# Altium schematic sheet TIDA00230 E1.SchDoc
size 431 x 279 mm; Date: Not shown in title block; ApprovedBy: Not shown in title block; CheckedBy: Not shown in title block; Author: Not shown in title block; CompanyName: Not shown in title block; DrawnBy: M. Chevrier; Engineer: Not shown in title block; Organization: Not shown in title block; Address1: Not shown in title block; Address2: Not shown in title block; Address3: Not shown in title block; Address4: Not shown in title block; DocumentNumber: 1; Revision: Use project parameter SCH_Rev; SheetNumber: 1; SheetTotal: 1; PageSetup: Record=PageOptions|CenterHorizontal=True|CenterVertical=True|PrintScale=0.94|XCorrection=1.00|YCorrection=1.00|PrintKind=0|BorderSize=5000000|LeftOffset=0|BottomOffset=0|Orientation=2|PaperLength=4200|PaperWidth=2970|Scale=100|PaperSource=7|PrintQuality=600|MediaType=1|DitherType=10|PaperKind=A3|PrintScaleMode=1
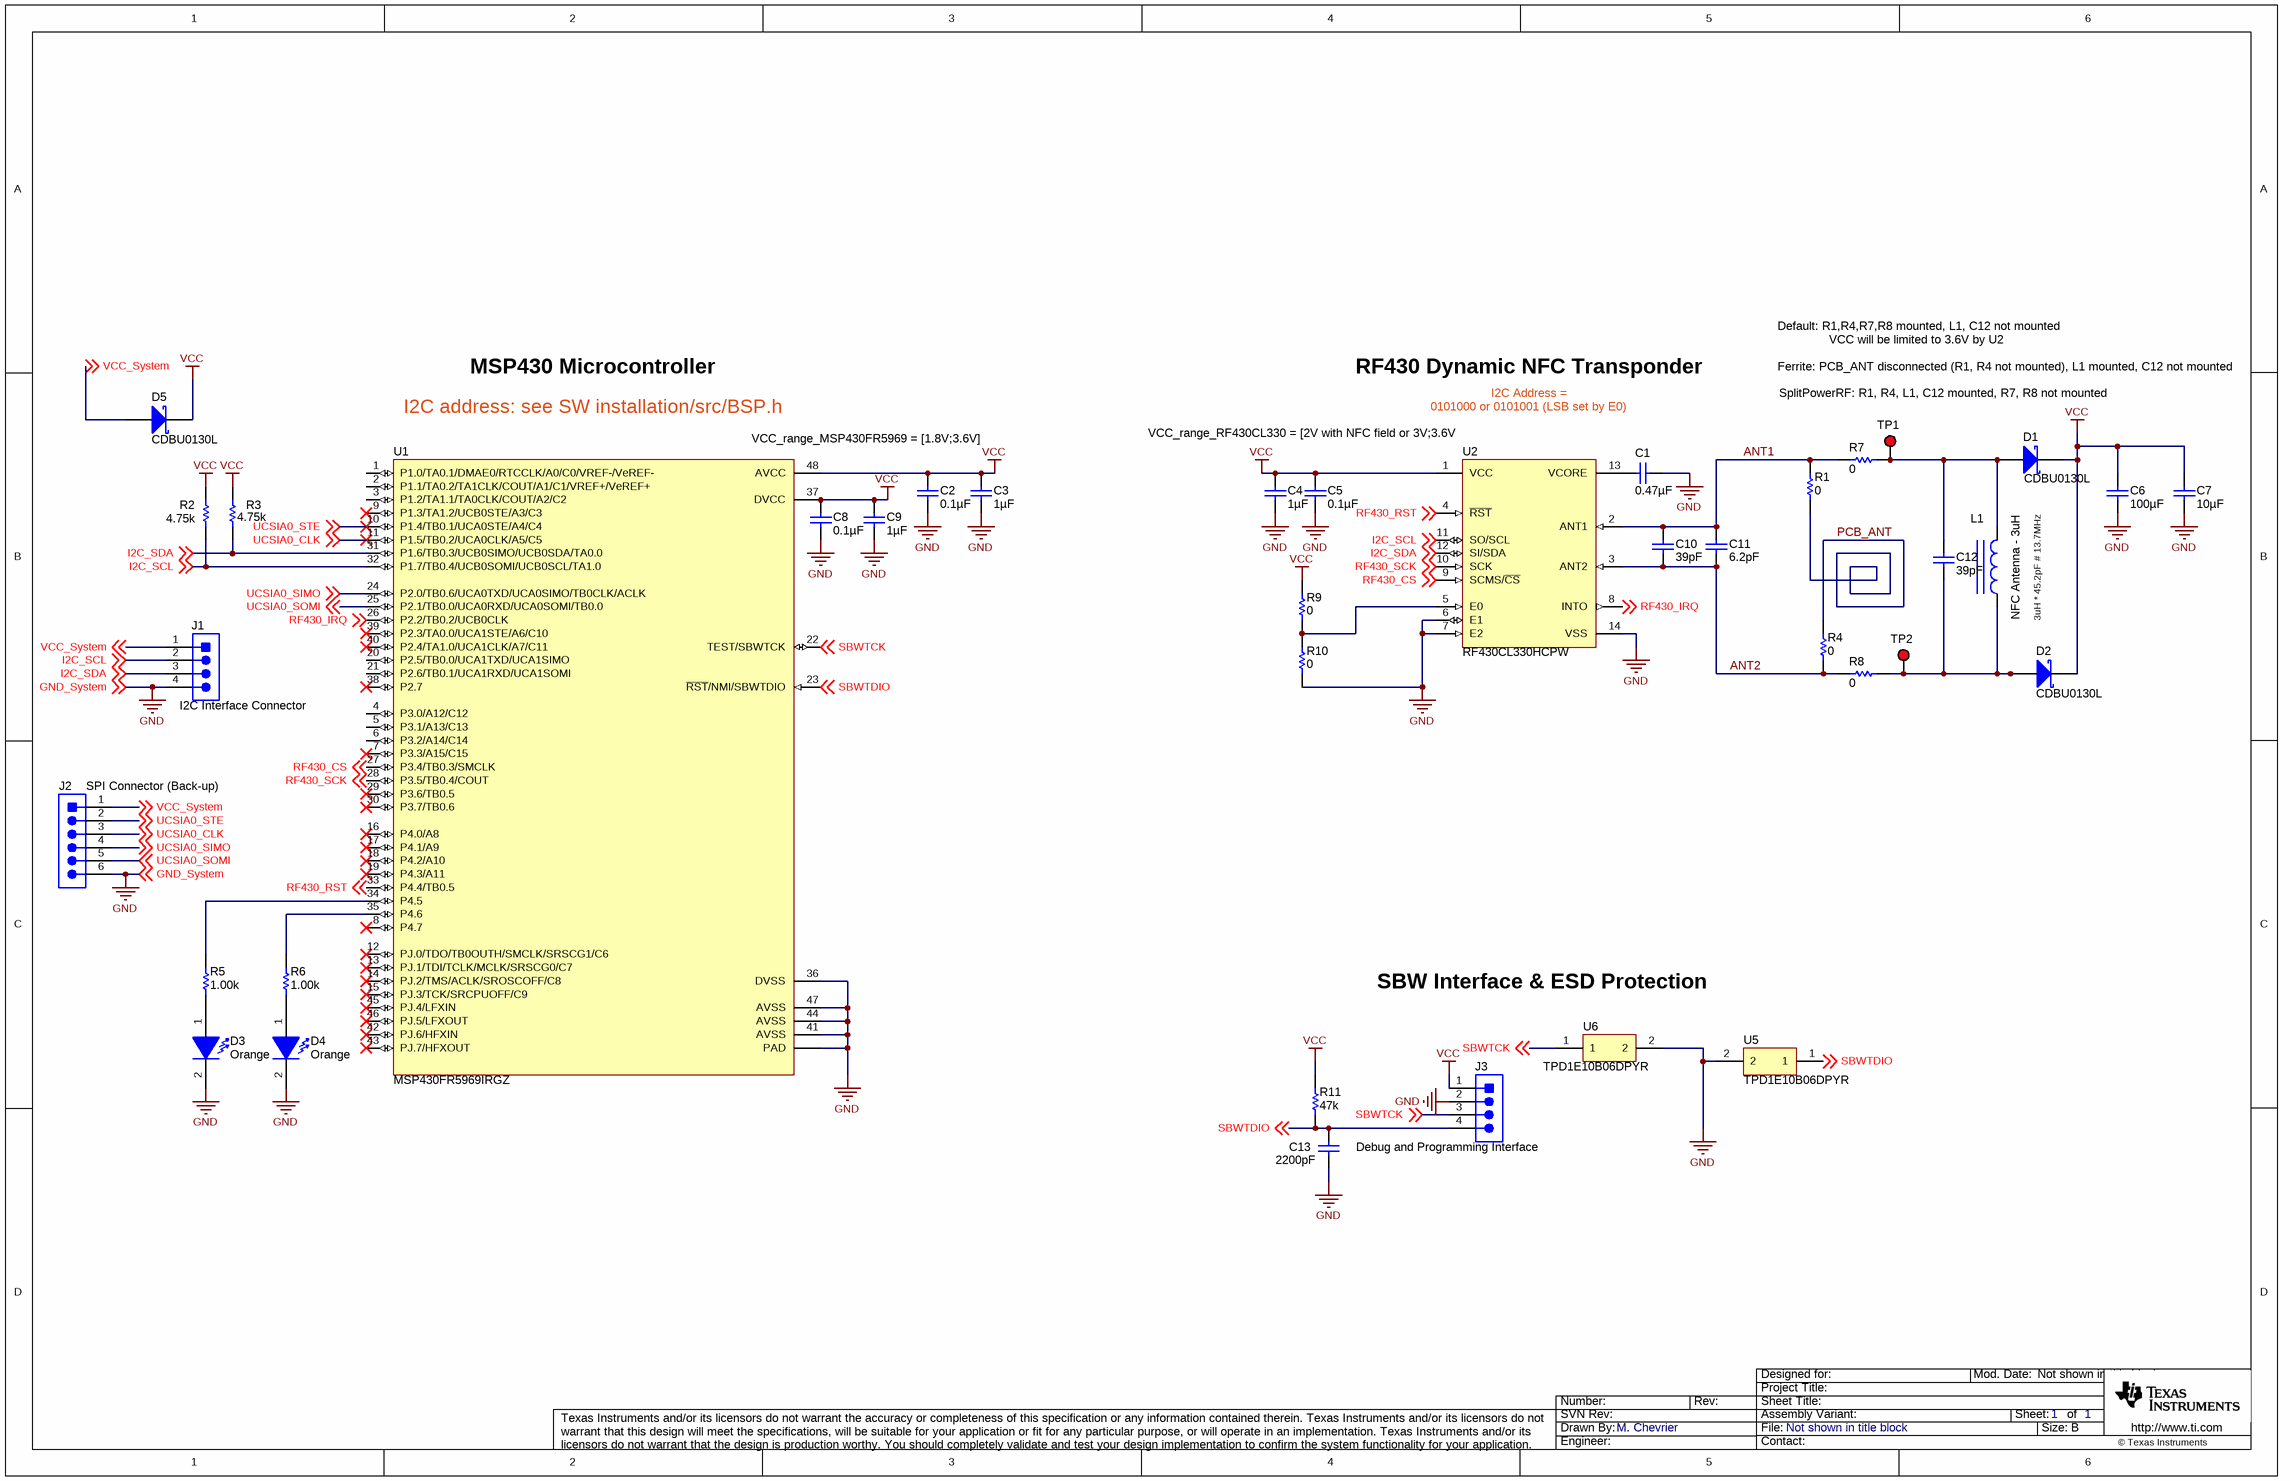
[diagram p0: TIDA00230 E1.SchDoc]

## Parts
C1  ValueDisplayed: 0.47µF  [0603S]  (hidden comment: GRM188R71E474KA12D)
C2  ValueDisplayed: 0.1µF  [0402S]  (hidden comment: GRM155R71C104KA88D)
C3  ValueDisplayed: 1µF  [0603S]  (hidden comment: GRM188R71C105KA12D)
C4  ValueDisplayed: 1µF  [0603S]  (hidden comment: GRM188R71C105KA12D)
C5  ValueDisplayed: 0.1µF  [0402S]  (hidden comment: GRM155R71C104KA88D)
C6  ValueDisplayed: 100µF  [1206_190]  (hidden comment: C3216X5R1A107M160AC)
C7  ValueDisplayed: 10µF  [0402S]  (hidden comment: CL05A106MP5NUNC)
C8  ValueDisplayed: 0.1µF  [0402S]  (hidden comment: GRM155R71C104KA88D)
C9  ValueDisplayed: 1µF  [0603S]  (hidden comment: GRM188R71C105KA12D)
C10  ValueDisplayed: 39pF  [0402S]  (hidden comment: GRM1555C1H390JA01D)
C11  ValueDisplayed: 6.2pF  [0402S]  (hidden comment: GRM1555C1E6R2CA01D)
C12  ValueDisplayed: 39pF  [0402]  (hidden comment: GRM1555C1H390JA01D)
C13  ValueDisplayed: 2200pF  [0402S]  (hidden comment: DNP)
D1  CDBU0130L  [SOD-523F]
D2  CDBU0130L  [SOD-523F]
D3  value Orange  [SML-31_Orange]  (hidden comment: SML-311DTT86)
D4  value Orange  [SML-31_Orange]  (hidden comment: SML-311DTT86)
D5  CDBU0130L  [SOD-523F]
J1  I2C Interface Connector  [Sullins_GRPB041VWCN]
J2  SPI Connector (Back-up)  [Sullins_GRPB061VWCN]
J3  Debug and Programming Interface  [Sullins_GRPB041VWCN]
L1  NFC Antenna - 3uH  [PREMO_SDTR1103-HF2]
R1  value 0  [0402S]  (hidden comment: CRCW04020000Z0ED)
R2  value 4.75k  [0402S]  (hidden comment: CRCW04024K75FKED)
R3  value 4.75k  [0402S]  (hidden comment: CRCW04024K75FKED)
R4  value 0  [0402S]  (hidden comment: CRCW04020000Z0ED)
R5  value 1.00k  [0402]  (hidden comment: CRCW04021K00FKED)
R6  value 1.00k  [0402]  (hidden comment: CRCW04021K00FKED)
R7  value 0  [0402S]  (hidden comment: CRCW04020000Z0ED)
R8  value 0  [0402S]  (hidden comment: CRCW04020000Z0ED)
R9  value 0  [0402S]  (hidden comment: CRCW04020000Z0ED)
R10  value 0  [0402S]  (hidden comment: CRCW04020000Z0ED)
R11  value 47k  [0402S]  (hidden comment: CRCW040247K0JNED)
TP1  5000  [Keystone5000]  (value not drawn)
TP2  5000  [Keystone5000]  (value not drawn)
U1  MSP430FR5969IRGZ  [RGZ0048B]
U2  RF430CL330HCPW  [PW0014A_N]
U5  TPD1E10B06DPYR  [DPY0002A_N]
U6  TPD1E10B06DPYR  [DPY0002A_N]

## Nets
GND: C1.2 C2.2 C3.2 C4.2 C5.2 C6.2 C7.2 C8.2 C9.2 C13.2 D3.2(K) D4.2(K) J1.4 J2.6 J3.2 R10.1 U1.36(DVSS) U1.41(AVSS) U1.44(AVSS) U1.47(AVSS) U1.49(PAD) U2.6(E1) U2.7(E2) U2.14(VSS) U5.2 U6.2 ; off-sheet GND_System  [also labelled GND_System]
VCC: C2.1 C3.1 C4.1 C5.1 C6.1 C7.1 C8.1 C9.1 D1.1(K) D2.1(K) D5.1(K) J3.1 R2.2 R3.2 R9.2 R11.2 U1.37(DVCC) U1.48(AVCC) U2.1(VCC)
ANT1: C10.1 C11.1 R1.2 R7.2 U2.2(ANT1)
ANT2: C10.2 C11.2 R4.1 R8.2 U2.3(ANT2)
I2C_SCL: J1.2 R2.1 U1.32(P1.7/TB0.4/UCB0SOMI/UCB0SCL/TA1.0) U2.11(SO/SCL) ; off-sheet I2C_SCL
I2C_SDA: J1.3 R3.1 U1.31(P1.6/TB0.3/UCB0SIMO/UCB0SDA/TA0.0) U2.12(SI/SDA) ; off-sheet I2C_SDA
PCB_ANT: R1.1 R4.2
RF430_CS: U1.27(P3.4/TB0.3/SMCLK) U2.9(SCMS/~{CS}) ; off-sheet RF430_CS
RF430_IRQ: U1.26(P2.2/TB0.2/UCB0CLK) U2.8(INTO) ; off-sheet RF430_IRQ
RF430_RST: U1.33(P4.4/TB0.5) U2.4(~{RST}) ; off-sheet RF430_RST
RF430_SCK: U1.28(P3.5/TB0.4/COUT) U2.10(SCK) ; off-sheet RF430_SCK
SBWTCK: J3.3 U1.22(TEST/SBWTCK) U6.1 ; off-sheet SBWTCK
SBWTDIO: C13.1 J3.4 R11.1 U1.23(~{RST}/NMI/SBWTDIO) U5.1 ; off-sheet SBWTDIO
UCSIA0_CLK: J2.3 U1.11(P1.5/TB0.2/UCA0CLK/A5/C5) ; off-sheet UCSIA0_CLK
UCSIA0_SIMO: J2.4 U1.24(P2.0/TB0.6/UCA0TXD/UCA0SIMO/TB0CLK/ACLK) ; off-sheet UCSIA0_SIMO
UCSIA0_SOMI: J2.5 U1.25(P2.1/TB0.0/UCA0RXD/UCA0SOMI/TB0.0) ; off-sheet UCSIA0_SOMI
UCSIA0_STE: J2.2 U1.10(P1.4/TB0.1/UCA0STE/A4/C4) ; off-sheet UCSIA0_STE
VCC_System: D5.2(A) J1.1 J2.1 ; off-sheet VCC_System
NetC1_1: C1.1 U2.13(VCORE)
NetC12_1: C12.1 D1.2(A) L1.2 R7.1 TP1.1
NetC12_2: C12.2 D2.2(A) L1.1 R8.1 TP2.1
NetD3_1: D3.1(A) R5.1
NetD4_1: D4.1(A) R6.1
NetR5_2: R5.2 U1.34(P4.5)
NetR6_2: R6.2 U1.35(P4.6)
NetR9_1: R9.1 R10.2 U2.5(E0)

Not connected (* = marked no-connect by the designer): U1 1(P1.0/TA0.1/DMAE0/RTCCLK/A0/C0/VREF-/VeREF-) 2(P1.1/TA0.2/TA1CLK/COUT/A1/C1/VREF+/VeREF+) 3(P1.2/TA1.1/TA0CLK/COUT/A2/C2) 4(P3.0/A12/C12) 5(P3.1/A13/C13) 6(P3.2/A14/C14) 7(P3.3/A15/C15)* 8(P4.7)* 9(P1.3/TA1.2/UCB0STE/A3/C3)* 12(PJ.0/TDO/TB0OUTH/SMCLK/SRSCG1/C6)* 13(PJ.1/TDI/TCLK/MCLK/SRSCG0/C7)* 14(PJ.2/TMS/ACLK/SROSCOFF/C8)* 15(PJ.3/TCK/SRCPUOFF/C9)* 16(P4.0/A8)* 17(P4.1/A9)* 18(P4.2/A10)* 19(P4.3/A11)* 20(P2.5/TB0.0/UCA1TXD/UCA1SIMO) 21(P2.6/TB0.1/UCA1RXD/UCA1SOMI) 29(P3.6/TB0.5)* 30(P3.7/TB0.6)* 38(P2.7)* 39(P2.3/TA0.0/UCA1STE/A6/C10)* 40(P2.4/TA1.0/UCA1CLK/A7/C11)* 42(PJ.6/HFXIN)* 43(PJ.7/HFXOUT)* 45(PJ.4/LFXIN)* 46(PJ.5/LFXOUT)*

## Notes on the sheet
- MSP430 Microcontroller
- RF430 Dynamic NFC Transponder
- VCC will be limited to 3.6V by U2
- Default: R1,R4,R7,R8 mounted, L1, C12 not mounted
- Ferrite: PCB_ANT disconnected (R1, R4 not mounted), L1 mounted, C12 not mounted
- I2C address: see SW installation/src/BSP.h
- VCC_range_MSP430FR5969 = [1.8V;3.6V]
- VCC_range_RF430CL330 = [2V with NFC field or 3V;3.6V
- I2C Address =
- 0101000 or 0101001 (LSB set by E0)
- SplitPowerRF: R1, R4, L1, C12 mounted, R7, R8 not mounted
- 3uH * 45.2pF # 13.7MHz
- SBW Interface & ESD Protection

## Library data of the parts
C1 = GRM188R71E474KA12D: CAP, CERM, 0.47uF, 25V, +/-10%, X7R, 0603; Manufacturer: MuRata; Polarized: N; CompType: Capacitor; U/M: EA; Cap_F: 0.00000047; Tolerance_%: 10; Value1: Unknown; VDC_V: 25; TaMin_C: -55; TaMax_C: 125; Cap_Case: 0603
C2 C5 C8 = GRM155R71C104KA88D: CAP, CERM, 0.1uF, 16V, +/-10%, X7R, 0402; Manufacturer: MuRata; Polarized: N; CompType: Capacitor; U/M: EA; Cap_F: 0.0000001; Tolerance_%: 10; Value1: Unknown; VDC_V: 16; TaMin_C: -55; TaMax_C: 125; Cap_Case: 0402
C3 C4 C9 = GRM188R71C105KA12D: CAP, CERM, 1uF, 16V, +/-10%, X7R, 0603; Manufacturer: MuRata; Polarized: N; CompType: Capacitor; U/M: EA; Cap_F: 0.000001; Tolerance_%: 10; ESR_Ohm: 0.011; Value1: 0.011 ohm; VDC_V: 16; TaMin_C: -55; TaMax_C: 125; Cap_Case: 0603
C6 = C3216X5R1A107M160AC: CAP, CERM, 100uF, 10V, +/-20%, X5R, 1206_190; Manufacturer: TDK; Polarized: N; CompType: Capacitor; U/M: EA; Cap_F: 0.0001; Tolerance_%: 20; Value1: Unknown; VDC_V: 10; TaMin_C: -55; TaMax_C: 85
C7 = CL05A106MP5NUNC: CAP, CERM, 10uF, 10V, +/-20%, X5R, 0402; Manufacturer: Samsung; Polarized: N; CompType: Capacitor; U/M: EA; Cap_F: 0.00001; Tolerance_%: 20; Value1: Unknown; VDC_V: 10; TaMin_C: -55; TaMax_C: 85; Cap_Case: 0402
C10 = GRM1555C1H390JA01D: CAP, CERM, 39pF, 50V, +/-5%, C0G/NP0, 0402; Manufacturer: MuRata; Polarized: N; CompType: Capacitor; U/M: EA; Cap_F: 0.000000000039; Tolerance_%: 5; Value1: Unknown; VDC_V: 50; TaMin_C: -55; TaMax_C: 125; Cap_Case: 0402
C11 = GRM1555C1E6R2CA01D: CAP, CERM, 6.2pF, 25V, +/-5%, C0G/NP0, 0402; Manufacturer: MuRata; Polarized: N; CompType: Capacitor; U/M: EA; Cap_F: 0.0000000000062; Tolerance_%: 5; Value1: Unknown; VDC_V: 25; TaMin_C: -55; TaMax_C: 125; Cap_Case: 0402
C12 = GRM1555C1H390JA01D: CAP, CERM, 39pF, 50V, +/-5%, C0G/NP0, 0402; Manufacturer: MuRata; Polarized: N; CompType: Capacitor; U/M: EA; Cap_F: 0.000000000039; Tolerance_%: 5; Value1: Unknown; VDC_V: 50; TaMin_C: -55; TaMax_C: 125
C13 = GRM155R70J222KA01D: CAP, CERM, 2200pF, 6.3V, +/-10%, X7R, 0402; Manufacturer: MuRata; Polarized: N; CompType: Capacitor; U/M: EA; Cap_F: 0.0000000022; Tolerance_%: 10; Value1: Unknown; VDC_V: 6.3; TaMin_C: -55; TaMax_C: 125; Cap_Case: 0402
D1 D2 D5 = CDBU0130L: Diode, Schottky, 35V, 0.1A, SOD-523F; Manufacturer: Comchip Technology; U/M: EA; Value2: V; Io_A: 0.1; Vr_V: 35; TJmax_C: 125
D3 D4 = SML-311DTT86: LED, Orange, SMD; Manufacturer: Rohm; Type: AlInGaP; Vf_V: 1.8; Value2: 1.8V; Io_A: 0.002; Value1: W; U/M: EA
J1 J3 = GRPB041VWCN-RC: Header, 50mil, 4x1, R/A, TH; Manufacturer: Sullins Connector Solutions; SymbolCreator: a0412235; U/M: EA
J2 = GRPB061VWCN-RC: Header, 50mil, 6x1, R/A, TH; Manufacturer: Sullins Connector Solutions; SymbolCreator: a0412235; U/M: EA
L1 = SDTR1103-HF2-0003K: Inductor, Wirewound, 3uH, 0.46 ohm, SMD; Manufacturer: Premo; Ind_H: 3.0E-6; ValueDisplayed: 3µH; DCR_ohm: 0.46; Value2: A
R1 R4 R7-R10 = CRCW04020000Z0ED: RES, 0 ohm, 5%, 0.063W, 0402; Manufacturer: Vishay-Dale; CompType: Resistor; Value_Code: 0000; Tolerance_%: 5; Power_W: 0.063; VDC_V: 50; TempCo: 200 ppm/C; EIA_Code: E24; U/M: EA
R2 R3 = CRCW04024K75FKED: RES, 4.75k ohm, 1%, 0.063W, 0402; Manufacturer: Vishay-Dale; CompType: Resistor; Res_ohm: 4750; Value_Code: 4k75; Tolerance_%: 1; Power_W: 0.063; VDC_V: 50; TempCo: 100 ppm/C; EIA_Code: E96; U/M: EA
R5 R6 = CRCW04021K00FKED: RES, 1.00k ohm, 1%, 0.063W, 0402; Manufacturer: Vishay-Dale; CompType: Resistor; Res_ohm: 1000; Value_Code: 1k00; Tolerance_%: 1; Power_W: 0.063; VDC_V: 50; TempCo: 100 ppm/C; EIA_Code: E96; U/M: EA
R11 = CRCW040247K0JNED: RES, 47k ohm, 5%, 0.063W, 0402; Manufacturer: Vishay-Dale; CompType: Resistor; Res_ohm: 47000; Value_Code: 47k0; Tolerance_%: 5; Power_W: 0.063; VDC_V: 50; TempCo: 200 ppm/C; EIA_Code: E24; U/M: EA
TP1 TP2 = 5000: Test Point, Miniature, Red, TH; Manufacturer: Keystone; CompType: Test Point Loop; U/M: EA
U1 = MSP430FR5969IRGZ: Mixed Signal Microcontroller, RGZ0048B; Alternate Manufacturer: None; Manufacturer: Texas Instruments; SymbolCreator: a0411947; CompType: IC; U/M: EA
U2 = RF430CL330HCPW: DYNAMIC NFC INTERFACE TRANSPONDER, PW0014A; Alternate Manufacturer: None; Manufacturer: Texas Instruments; SymbolCreator: a0141285; CompType: IC; U/M: EA
U5 U6 = TPD1E10B06DPYR: ESD in 0402 Package with 10 pF Capacitance and 6 V Breakdown, 1 Channel, -40 to +125 degC, 2-pin X2SON (DPY), Green (RoHS & no Sb/Br); Manufacturer: Texas Instruments; Alternate Manufacturer: None; Alternate PartNumber: Equivalent; Breakdown Voltage(Min)(V): 6; Eco-Plan: TBD; IEC 61000-4-2 Air-Gap(+/- kV): 30; IO Capacitance(Typ)(pF): 10; SubFamily: ESD Solution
